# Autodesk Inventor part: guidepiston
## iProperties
Shininess: 20.0
Length Units: 11269
Angle Units: 11279
Time Units: 11290
Mass Units: 11283
Length Display Precision: 3
Angle Display Precision: 2
Compacted: True
Created: 2002-07
Part Number: guidepiston
Material: Par défaut
Document SubType Name: Modélisation
Designer: robert
Density: 1 g/cm^3
Density: 0.0
Volumn: 0.0
Area: 0.0
PropertySet Name: Model Information
Control State: 0
Master: False
Checked Out: False
Author: robert
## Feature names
1. Révolution1 [Revolution]
2. Extrusion1
